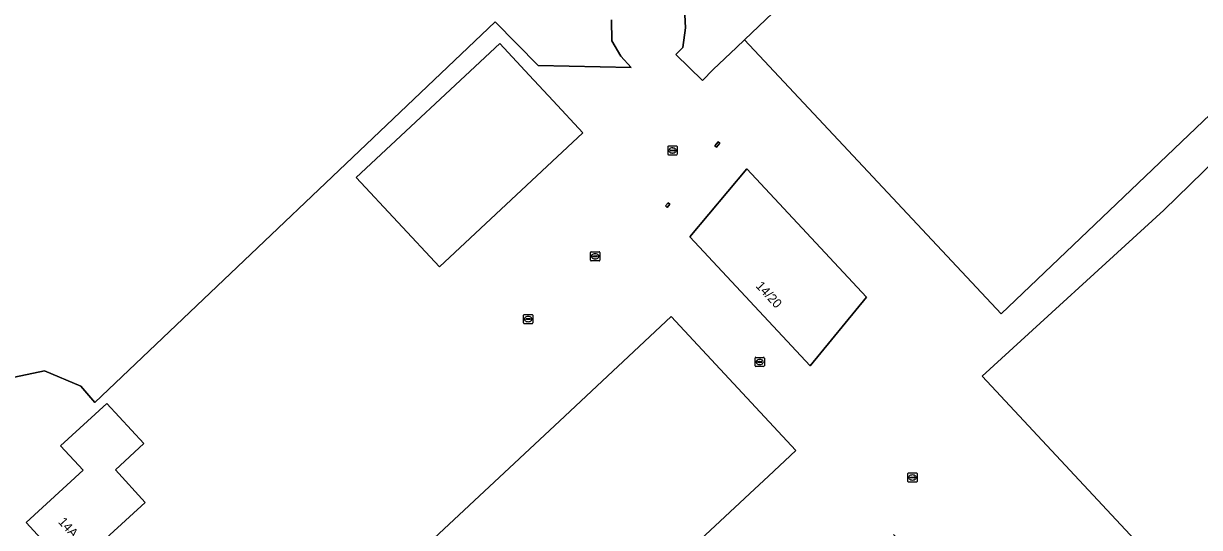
# Model space of a CAD drawing. Extents: x 157132 to 159279, y 384991 to 386650.
# Drawn here: x 157700.2 to 157828.4, y 386063.2 to 386118.1 of the extents above; entities that cross this region are included whole.
import ezdxf

# ---------------------------------------------------------------- set-up
doc = ezdxf.new("R2010")
doc.units = 0
for name, color, linetype in [('IMGEO_Bouwland', 7, 'Continuous'), ('IMGEO_Erf', 7, 'Continuous'), ('IMGEO_Grasland_agrarisch', 7, 'Continuous'), ('IMGEO_Kolk', 7, 'Continuous'), ('IMGEO_Pand', 7, 'Continuous'), ('IMGEO_Pand_nummerreeks', 7, 'Continuous')]:
    doc.layers.add(name, color=color, linetype=linetype)

msp = doc.modelspace()

# ---------------------------------------------------------------- linework, layer by layer
at = {"layer": 'IMGEO_Bouwland'}
for points in [[(157772.31, 386119.08), (157772.38, 386117.69), (157772.08, 386115.54), (157771.31, 386114.76), (157774.22, 386111.95), (157775.39, 386113.12), (157777.95, 386115.55), (157778.82, 386116.38), (157896.14, 386228.23)], [(157698, 386179.78), (157612.51, 386098.09), (157675.97, 386060.01), (157698.54, 386079.47), (157702.5, 386080.31), (157706.46, 386078.63), (157707.98, 386076.86), (157751.64, 386118.34), (157756.3, 386113.56), (157766.45, 386113.36), (157765.33, 386114.6), (157764.35, 386116.27), (157764.32, 386118.56)]]:
    msp.add_lwpolyline(points, dxfattribs=at)
msp.add_lwpolyline([(157907.89, 386100.62), (157908.11, 386103.25), (157909.47, 386103.17), (157972.32, 386163.18), (157975.23, 386165.96), (157973.79, 386167.47), (157936.15, 386206.72), (157933.34, 386204.01), (157921.22, 386191.28), (157874.85, 386146.92), (157824.5, 386097.81), (157804.71, 386079.73), (157842.48, 386039.2), (157906.64, 386100.46)], close=True, dxfattribs=at)
at = {"layer": 'IMGEO_Erf'}
for points in [[(157931.71, 386205.71), (157806.77, 386086.5), (157778.82, 386116.38), (157777.95, 386115.55), (157775.39, 386113.12), (157774.22, 386111.95), (157771.31, 386114.76), (157772.08, 386115.54), (157772.38, 386117.69), (157772.31, 386119.08)], [(157795.04, 386062.45), (157829.15, 386025.88), (157829.85, 386025.2), (157833.54, 386028.71), (157834.29, 386029.42), (157835.6, 386030.67), (157834.62, 386031.7), (157842.48, 386039.2), (157804.71, 386079.73), (157824.5, 386097.81), (157874.85, 386146.92), (157921.22, 386191.28)], [(157764.32, 386118.56), (157764.35, 386116.27), (157765.33, 386114.6), (157766.45, 386113.36), (157756.3, 386113.56), (157751.64, 386118.34), (157707.98, 386076.86), (157706.46, 386078.63), (157702.5, 386080.31), (157698.54, 386079.47), (157675.97, 386060.01), (157674.23, 386058.56), (157697.5, 386045.31), (157698.08, 386044.98), (157701.49, 386043.04), (157701.96, 386042.77), (157740.31, 386020.61), (157741.27, 386021.51), (157743.7, 386020.1), (157742.74, 386019.2), (157754.1, 386012.64)], [(157754.1, 386012.64), (157762.5, 386020.57), (157756.42, 386026.96), (157751.74, 386031.88), (157747.91, 386035.89), (157747.31, 386036.52), (157741.77, 386042.33), (157733.43, 386051.27), (157759.21, 386075.36), (157770.8, 386086.2), (157784.41, 386071.6), (157781.41, 386068.8), (157779.91, 386067.41), (157769.18, 386057.41), (157767.6, 386059.12), (157765.18, 386056.82), (157761.5, 386060.77), (157753.05, 386052.87), (157742.12, 386042.66), (157747.66, 386036.85), (157758.43, 386047.1), (157759.08, 386047.73), (157759.21, 386047.85)]]:
    msp.add_lwpolyline(points, dxfattribs=at)
for points in [[(157752.12, 386115.98), (157755.33, 386112.53), (157757.96, 386109.72), (157761.2, 386106.24), (157745.56, 386091.64), (157736.47, 386101.38)], [(157775.93, 386105.24), (157776.1, 386105.09), (157775.75, 386104.66), (157775.57, 386104.81)], [(157779.05, 386102.32), (157792.11, 386088.33), (157785.96, 386080.85), (157772.86, 386094.9)], [(157770.48, 386098.62), (157770.67, 386098.46), (157770.38, 386098.11), (157770.19, 386098.26)], [(157709.32, 386076.75), (157713.34, 386072.36), (157710.23, 386069.52), (157713.49, 386065.96), (157705.35, 386058.51), (157700.52, 386063.78), (157706.72, 386069.46), (157704.27, 386072.12)]]:
    msp.add_lwpolyline(points, close=True, dxfattribs=at)
at = {"layer": 'IMGEO_Grasland_agrarisch'}
msp.add_lwpolyline([(157908.63, 386215.04), (157898.31, 386225.94), (157896.14, 386228.23), (157778.82, 386116.38), (157806.77, 386086.5), (157931.71, 386205.71), (157917.17, 386220.94), (157912.61, 386216.91), (157917.18, 386212.42), (157913.9, 386209.47), (157914.39, 386208.98), (157910.06, 386204.6), (157907.66, 386207.24), (157909.29, 386208.84), (157907.66, 386210.54), (157910.44, 386213.13)], close=True, dxfattribs=at)
at = {"layer": 'IMGEO_Kolk'}
for p, q in [((157770.47, 386103.89), (157770.47, 386104.74)), ((157770.54, 386104.81), (157771.39, 386104.81)), ((157770.73, 386104.31), (157770.73, 386104.32)), ((157770.77, 386104.36), (157771.17, 386104.36)), ((157771.16, 386104.27), (157770.77, 386104.27)), ((157770.98, 386104.03), (157770.95, 386104.03)), ((157770.96, 386104.59), (157770.98, 386104.59)), ((157771.21, 386104.32), (157771.21, 386104.31)), ((157771.47, 386104.74), (157771.47, 386103.89)), ((157771.39, 386103.81), (157770.54, 386103.81)), ((157762.02, 386092.35), (157762.02, 386093.2)), ((157762.1, 386093.28), (157762.95, 386093.28)), ((157762.28, 386092.77), (157762.28, 386092.78)), ((157762.72, 386092.73), (157762.32, 386092.73)), ((157762.33, 386092.82), (157762.72, 386092.82)), ((157762.51, 386093.06), (157762.54, 386093.06)), ((157762.53, 386092.5), (157762.51, 386092.5)), ((157762.77, 386092.78), (157762.77, 386092.77)), ((157763.03, 386093.2), (157763.03, 386092.35)), ((157762.95, 386092.28), (157762.1, 386092.28)), ((157754.73, 386085.51), (157754.73, 386086.36)), ((157754.8, 386086.43), (157755.65, 386086.43)), ((157755.22, 386086.21), (157755.24, 386086.21)), ((157755.73, 386086.36), (157755.73, 386085.51)), ((157755.65, 386085.43), (157754.8, 386085.43)), ((157754.99, 386085.93), (157754.99, 386085.94)), ((157755.03, 386085.98), (157755.43, 386085.98)), ((157755.42, 386085.89), (157755.03, 386085.89)), ((157755.24, 386085.65), (157755.21, 386085.65)), ((157755.47, 386085.94), (157755.47, 386085.93)), ((157779.97, 386080.84), (157779.97, 386081.69)), ((157780.04, 386081.76), (157780.89, 386081.76)), ((157780.22, 386081.26), (157780.22, 386081.27)), ((157780.66, 386081.22), (157780.26, 386081.22)), ((157780.27, 386081.31), (157780.66, 386081.31)), ((157780.45, 386081.54), (157780.48, 386081.54)), ((157780.48, 386080.98), (157780.45, 386080.98)), ((157780.71, 386081.27), (157780.71, 386081.26)), ((157780.97, 386081.69), (157780.97, 386080.84)), ((157780.89, 386080.76), (157780.04, 386080.76)), ((157796.62, 386068.25), (157796.62, 386069.1)), ((157796.69, 386069.18), (157797.54, 386069.18)), ((157797.54, 386068.17), (157796.69, 386068.17)), ((157796.87, 386068.67), (157796.87, 386068.68)), ((157797.31, 386068.63), (157796.91, 386068.63)), ((157796.92, 386068.72), (157797.31, 386068.72)), ((157797.1, 386068.95), (157797.13, 386068.95)), ((157797.13, 386068.4), (157797.1, 386068.4)), ((157797.36, 386068.68), (157797.36, 386068.67)), ((157797.62, 386069.1), (157797.62, 386068.25))]:
    msp.add_line(p, q, dxfattribs=at)
for points in [[(157770.47, 386103.89), (157770.47, 386104.74)], [(157770.54, 386104.81), (157771.39, 386104.81)], [(157771.47, 386104.74), (157771.47, 386103.89)], [(157771.39, 386103.81), (157770.54, 386103.81)], [(157762.02, 386092.35), (157762.02, 386093.2)], [(157762.1, 386093.28), (157762.95, 386093.28)], [(157763.03, 386093.2), (157763.03, 386092.35)], [(157762.95, 386092.28), (157762.1, 386092.28)], [(157754.73, 386085.51), (157754.73, 386086.36)], [(157754.8, 386086.43), (157755.65, 386086.43)], [(157755.73, 386086.36), (157755.73, 386085.51)], [(157755.65, 386085.43), (157754.8, 386085.43)], [(157779.97, 386080.84), (157779.97, 386081.69)], [(157780.04, 386081.76), (157780.89, 386081.76)], [(157780.97, 386081.69), (157780.97, 386080.84)], [(157780.89, 386080.76), (157780.04, 386080.76)], [(157796.62, 386068.25), (157796.62, 386069.1)], [(157796.69, 386069.18), (157797.54, 386069.18)], [(157797.54, 386068.17), (157796.69, 386068.17)], [(157797.62, 386069.1), (157797.62, 386068.25)]]:
    msp.add_lwpolyline(points, dxfattribs=at)
for centre, radius, start, end in [((157770.54, 386104.74), 0.0765, 91.552, 178.448), ((157770.54, 386104.74), 0.0765, 91.552, 178.448), ((157770.77, 386104.32), 0.0403, 85.8775, 175.7526), ((157770.76, 386104.31), 0.0366, 178.938, 274.7102), ((157771.17, 386104.31), 0.043, 264.8664, 352.4533), ((157771.17, 386104.32), 0.0386, 1.7309, 96.639), ((157771.39, 386104.74), 0.0765, 1.552, 88.448), ((157771.39, 386104.74), 0.0765, 1.552, 88.448), ((157770.54, 386103.89), 0.0765, 181.552, 268.448), ((157770.54, 386103.89), 0.0765, 181.552, 268.448), ((157771.39, 386103.89), 0.0765, 271.552, 358.448), ((157771.39, 386103.89), 0.0765, 271.552, 358.448), ((157762.1, 386093.2), 0.0765, 91.552, 178.448), ((157762.1, 386093.2), 0.0765, 91.552, 178.448), ((157762.32, 386092.78), 0.0403, 85.8775, 175.7526), ((157762.32, 386092.77), 0.0366, 178.938, 274.7102), ((157762.73, 386092.78), 0.0386, 1.7309, 96.639), ((157762.72, 386092.78), 0.043, 264.8664, 352.4533), ((157762.95, 386093.2), 0.0765, 1.552, 88.448), ((157762.95, 386093.2), 0.0765, 1.552, 88.448), ((157762.1, 386092.35), 0.0765, 181.552, 268.448), ((157762.1, 386092.35), 0.0765, 181.552, 268.448), ((157762.95, 386092.35), 0.0765, 271.552, 358.448), ((157762.95, 386092.35), 0.0765, 271.552, 358.448), ((157754.8, 386086.36), 0.0765, 91.552, 178.448), ((157754.8, 386086.36), 0.0765, 91.552, 178.448), ((157755.65, 386086.36), 0.0765, 1.552, 88.448), ((157755.65, 386086.36), 0.0765, 1.552, 88.448), ((157754.8, 386085.51), 0.0765, 181.552, 268.448), ((157754.8, 386085.51), 0.0765, 181.552, 268.448), ((157755.03, 386085.94), 0.0403, 85.8775, 175.7526), ((157755.02, 386085.93), 0.0366, 178.938, 274.7102), ((157755.43, 386085.93), 0.043, 264.8664, 352.4533), ((157755.43, 386085.94), 0.0386, 1.7309, 96.639), ((157755.65, 386085.51), 0.0765, 271.552, 358.448), ((157755.65, 386085.51), 0.0765, 271.552, 358.448), ((157780.04, 386081.69), 0.0765, 91.552, 178.448), ((157780.04, 386081.69), 0.0765, 91.552, 178.448), ((157780.26, 386081.27), 0.0403, 85.8775, 175.7526), ((157780.26, 386081.26), 0.0366, 178.938, 274.7102), ((157780.67, 386081.27), 0.0386, 1.7309, 96.639), ((157780.67, 386081.26), 0.043, 264.8664, 352.4533), ((157780.89, 386081.69), 0.0765, 1.552, 88.448), ((157780.89, 386081.69), 0.0765, 1.552, 88.448), ((157780.04, 386080.84), 0.0765, 181.552, 268.448), ((157780.04, 386080.84), 0.0765, 181.552, 268.448), ((157780.89, 386080.84), 0.0765, 271.552, 358.448), ((157780.89, 386080.84), 0.0765, 271.552, 358.448), ((157796.69, 386069.1), 0.0765, 91.552, 178.448), ((157796.69, 386069.1), 0.0765, 91.552, 178.448), ((157796.69, 386068.25), 0.0765, 181.552, 268.448), ((157796.69, 386068.25), 0.0765, 181.552, 268.448), ((157796.91, 386068.68), 0.0403, 85.8775, 175.7526), ((157796.91, 386068.67), 0.0366, 178.938, 274.7102), ((157797.32, 386068.68), 0.0386, 1.7309, 96.639), ((157797.32, 386068.67), 0.043, 264.8664, 352.4533), ((157797.54, 386069.1), 0.0765, 1.552, 88.448), ((157797.54, 386069.1), 0.0765, 1.552, 88.448), ((157797.54, 386068.25), 0.0765, 271.552, 358.448), ((157797.54, 386068.25), 0.0765, 271.552, 358.448)]:
    msp.add_arc(centre, radius, start, end, dxfattribs=at)
for centre, major_axis, ratio, start_param, end_param in [((157770.95, 386104.31), (-0.387, 0.002), 0.722429, 4.712389, 7.853982), ((157770.98, 386104.31), (-0.39, 0.002), 0.717154, 1.570796, 4.712389), ((157762.51, 386092.78), (-0.387, 0.002), 0.722429, 4.712389, 7.853982), ((157762.54, 386092.78), (-0.39, 0.002), 0.717154, 1.570796, 4.712389), ((157755.21, 386085.93), (-0.387, 0.002), 0.722429, 4.712389, 7.853982), ((157755.24, 386085.93), (-0.39, 0.002), 0.717154, 1.570796, 4.712389), ((157780.45, 386081.26), (-0.387, 0.002), 0.722429, 4.712389, 7.853982), ((157780.48, 386081.26), (-0.39, 0.002), 0.717154, 1.570796, 4.712389), ((157797.1, 386068.67), (-0.387, 0.002), 0.722429, 4.712389, 7.853982), ((157797.13, 386068.67), (-0.39, 0.002), 0.717154, 1.570796, 4.712389)]:
    msp.add_ellipse(centre, major_axis=major_axis, ratio=ratio, start_param=start_param, end_param=end_param, dxfattribs=at)
at = {"layer": 'IMGEO_Pand'}
for points in [[(157757.96, 386109.72), (157755.33, 386112.53), (157752.12, 386115.98), (157736.47, 386101.38), (157745.56, 386091.64), (157761.2, 386106.24)], [(157776.1, 386105.09), (157775.93, 386105.24), (157775.57, 386104.81), (157775.75, 386104.66)], [(157779.05, 386102.32), (157772.86, 386094.9), (157785.96, 386080.85), (157792.11, 386088.33)], [(157770.67, 386098.46), (157770.48, 386098.62), (157770.19, 386098.26), (157770.38, 386098.11)], [(157742.12, 386042.66), (157753.05, 386052.87), (157761.5, 386060.77), (157765.18, 386056.82), (157767.6, 386059.12), (157769.18, 386057.41), (157779.91, 386067.41), (157781.41, 386068.8), (157784.41, 386071.6), (157770.8, 386086.2), (157759.21, 386075.36), (157733.43, 386051.27), (157741.77, 386042.33)], [(157705.35, 386058.51), (157713.49, 386065.96), (157710.23, 386069.52), (157713.34, 386072.36), (157709.32, 386076.75), (157704.27, 386072.12), (157706.72, 386069.46), (157700.52, 386063.78)]]:
    msp.add_lwpolyline(points, close=True, dxfattribs=at)

# ---------------------------------------------------------------- texts
at = {"layer": 'IMGEO_Pand_nummerreeks'}
for s, rotation, p in [('14/20', 312.7768, (157779.97, 386089.49)), ('14A', 312.4819, (157703.94, 386063.78))]:
    msp.add_text(s, height=1, rotation=rotation, dxfattribs=at).set_placement(p)

doc.saveas('drawing.dxf')
